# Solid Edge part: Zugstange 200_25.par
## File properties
Username: ahadarics
Dokumentum tartalom típus: 0
Author: ahadarics
Last saved by: ahadarics
Revision: 78
Sűrűség: 0,000 kg/m^3
Pontosság: 0,990
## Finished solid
Body 1: solid body, 5 faces, 7 edges, 4 vertices.
  Faces by surface: cone 2, plane 2, cylinder 1
  Edges by curve: circle 5, line 2
Bounding box of the edges (mm): 16.000 x 16.000 x 155.000, from (-8, -8, -77.5) to (8, 8, 77.5).
Cylindrical faces by radius (mm): R8 x1
Conical faces (half-angle, radius in mm at the cone's reference point): 45 deg R7.5 x2
Planar faces by outward normal: +z 1, -z 1
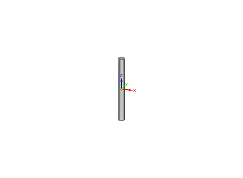
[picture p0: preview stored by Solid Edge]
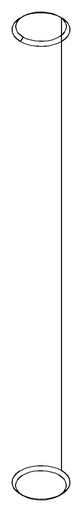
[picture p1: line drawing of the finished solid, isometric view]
